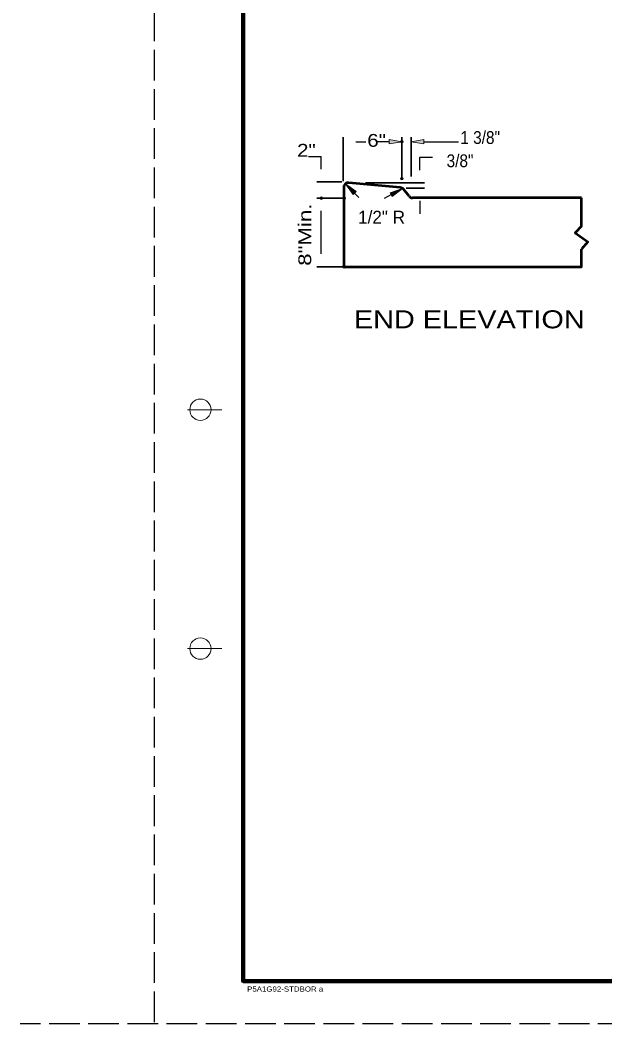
# Model space of a CAD drawing. Extents: x 75.6 to 110.9, y 28 to 50.
# Drawn here: x 75.6 to 82.46, y 27.98 to 39.75 of the extents above; entities that cross this region are included whole.
import ezdxf

# ---------------------------------------------------------------- set-up
doc = ezdxf.new("R2010")
doc.units = 0
doc.header["$LTSCALE"] = 0.06
doc.header["$PDMODE"] = 32
doc.header["$PDSIZE"] = 0.03
doc.linetypes.add('LONG_DASHED', pattern=[7.5, 6, -1.5])
doc.layers.add('1', color=7, linetype='Continuous', lineweight=25)
doc.layers.add('3', color=7, linetype='Continuous', lineweight=13)

msp = doc.modelspace()

# ---------------------------------------------------------------- hatches: boundary and pattern name
at = {"layer": '3'}
for points in [[(79.93083, 38.29692), (79.93083, 38.34692), (80.08083, 38.32192), (80.08083, 38.32192)], [(80.33792, 38.29692), (80.33792, 38.34692), (80.18792, 38.32192), (80.18792, 38.32192)], [(79.50733, 37.704), (79.54317, 37.73883), (79.42067, 37.82892), (79.42067, 37.82892)], [(79.94292, 37.72433), (79.96683, 37.68033), (80.08658, 37.77408), (80.08658, 37.77408)]]:
    msp.add_hatch(color=256, dxfattribs=at).paths.add_polyline_path(points)

# ---------------------------------------------------------------- linework, layer by layer
at = {"layer": '1', "linetype": 'LONG_DASHED'}
for p, q in [((77.175, 49.97992), (77.175, 27.97992)), ((110.8, 27.97992), (75.6, 27.97992))]:
    msp.add_line(p, q, dxfattribs=at)
at = {"layer": '1', "lineweight": 158}
msp.add_line((78.21667, 49.47992), (78.21667, 28.47992), dxfattribs=at)
at = {"layer": '1', "lineweight": 53}
for p, q in [((79.39942, 37.78792), (79.39942, 36.85617)), ((80.06083, 37.78442), (79.4585, 37.84167)), ((80.164, 37.68367), (80.09758, 37.76483)), ((82.18875, 37.66383), (80.20583, 37.66383)), ((82.18875, 37.33008), (82.18875, 37.66383))]:
    msp.add_line(p, q, dxfattribs=at)
at = {"layer": '1', "lineweight": 13}
for p, q in [((77.96667, 35.17992), (77.56667, 35.17992)), ((77.96667, 32.37992), (77.56667, 32.37992))]:
    msp.add_line(p, q, dxfattribs=at)
at = {"layer": '1', "lineweight": 158}
msp.add_lwpolyline([(110.71667, 49.47992), (110.71667, 28.47992), (78.21667, 28.47992)], dxfattribs=at)
at = {"layer": '1', "lineweight": 53}
for points in [[(82.18875, 37.33008), (82.11342, 37.25467), (82.26417, 37.14692), (82.18875, 37.06075)], [(79.39942, 36.85617), (82.18875, 36.85617), (82.18875, 37.06075)]]:
    msp.add_lwpolyline(points, dxfattribs=at)
at = {"layer": '1', "lineweight": 13}
for centre in [(77.71667, 35.17992), (77.71667, 32.37992)]:
    msp.add_circle(centre, 0.125, dxfattribs=at)
at = {"layer": '1', "lineweight": 53}
for centre, start, end in [((79.4534, 37.7879), 84.57214, 180), ((80.05575, 37.73065), 39.292, 84.57214), ((80.2058, 37.7178), 219.292, 270)]:
    msp.add_arc(centre, 0.054, start, end, dxfattribs=at)
at = {"layer": '1'}
msp.add_point((78.21667, 28.47992), dxfattribs=at)
at = {"layer": '3', "lineweight": 35}
for p, q in [((79.38975, 37.85917), (79.38975, 38.37592)), ((80.08083, 37.90817), (80.08083, 38.37592)), ((80.18792, 37.91275), (80.18792, 38.37592)), ((79.37733, 37.84992), (79.08067, 37.84992)), ((79.65283, 37.84042), (80.34433, 37.84042)), ((80.12983, 37.778), (80.34433, 37.778)), ((79.38642, 37.66042), (79.08067, 37.66042)), ((79.38067, 36.85617), (79.08067, 36.85617))]:
    msp.add_line(p, q, dxfattribs=at)
at = {"layer": '3', "lineweight": 25}
for p, q in [((79.53975, 38.32192), (79.65558, 38.32192)), ((79.93083, 38.32192), (79.78083, 38.32192)), ((80.33792, 38.32192), (80.48792, 38.32192)), ((80.48792, 38.32192), (80.74458, 38.32192)), ((78.98467, 38.14992), (79.13467, 38.14992)), ((79.13467, 37.99992), (79.13467, 38.14992)), ((79.42067, 37.82892), (79.57692, 37.66858)), ((80.08658, 37.77417), (79.87392, 37.65475)), ((80.29033, 37.628), (80.29033, 37.478)), ((79.13467, 37.00617), (79.13467, 37.51042))]:
    msp.add_line(p, q, dxfattribs=at)
at = {"layer": '3'}
for p, q in [((79.81183, 38.32192), (79.93083, 38.32192)), ((80.08083, 38.30317), (80.08083, 38.26792)), ((80.18792, 38.32192), (80.188, 38.32192)), ((80.18792, 37.894), (80.188, 37.894)), ((79.38975, 37.84042), (79.38983, 37.84042)), ((80.29033, 37.778), (80.29042, 37.778))]:
    msp.add_line(p, q, dxfattribs=at)
for points in [[(79.93083, 38.29692), (79.93083, 38.34692), (80.08083, 38.32192), (80.08083, 38.32192)], [(80.33792, 38.29692), (80.33792, 38.34692), (80.18792, 38.32192), (80.18792, 38.32192)], [(79.50733, 37.704), (79.54317, 37.73883), (79.42067, 37.82892), (79.42067, 37.82892)], [(79.94292, 37.72433), (79.96683, 37.68033), (80.08658, 37.77408), (80.08658, 37.77408)]]:
    msp.add_lwpolyline(points, close=True, dxfattribs=at)
at = {"layer": '3', "lineweight": 25}
msp.add_lwpolyline([(80.29033, 37.99042), (80.29033, 38.14042), (80.44033, 38.14042)], dxfattribs=at)
at = {"layer": '3'}
for p in [(80.08083, 38.32192), (80.08083, 37.88942), (79.13467, 37.66042), (79.40517, 37.66042), (79.39942, 36.85617)]:
    msp.add_point(p, dxfattribs=at)

# ---------------------------------------------------------------- texts
at = {"layer": '1', "width": 1.15}
msp.add_text('P5A1G92-STDBOR a', height=0.06, dxfattribs=at).set_placement((78.26467, 28.35892))
at = {"layer": '3'}
for s, height, width, p in [('6"', 0.15, 1.2, (79.67408, 38.26258)), ('1 3/8"', 0.15, 0.9, (80.766, 38.296)), ('2"', 0.15, 1.2, (78.8505, 38.1465)), ('3/8"', 0.15, 0.9, (80.60525, 38.02342)), ('END ELEVATION ', 0.2109, 1.2, (79.51708, 36.13458))]:
    msp.add_text(s, height=height, dxfattribs=dict(at, width=width)).set_placement(p)
at = {"layer": '3', "width": 1.3}
msp.add_text('8"Min.', height=0.15, rotation=90, dxfattribs=at).set_placement((79.016, 36.86717))
at = {"layer": '3'}
msp.add_text('1/2" R', height=0.15, dxfattribs=at).set_placement((79.56658, 37.3625))

doc.saveas('drawing.dxf')
